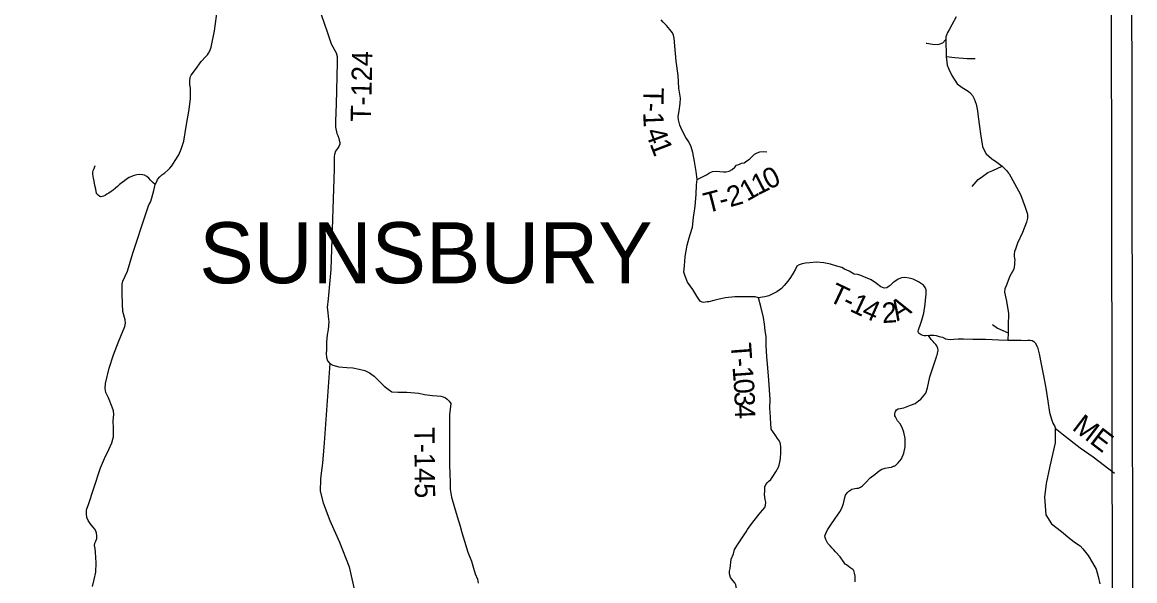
# Model space of a CAD drawing. Extents: x -15 to 405, y -40 to 87.
# Drawn here: x -9.096 to -5.813, y 38.387 to 40.035 of the extents above; entities that cross this region are included whole.
import ezdxf

# ---------------------------------------------------------------- set-up
doc = ezdxf.new("R2010")
doc.units = 0
for name, color, linetype in [('GM_P_State_Location', 7, 'Continuous'), ('GM_X_County_Road_Text', 7, 'Continuous'), ('GM_X_Major_Lake_Text', 7, 'Continuous'), ('GM_X_Minor_Lake', 7, 'Continuous'), ('GM_X_Minor_River', 7, 'Continuous'), ('GM_X_State_Location', 7, 'Continuous'), ('GM_X_Township_Text', 7, 'Continuous')]:
    doc.layers.add(name, color=color, linetype=linetype)

msp = doc.modelspace()

# ---------------------------------------------------------------- linework, layer by layer
at = {"layer": 'GM_P_State_Location'}
for points in [[(-8.2139, 40.0584), (-8.1968, 40.0073), (-8.1843, 39.9714), (-8.1696, 39.9447), (-8.167, 39.9339), (-8.1672, 39.9163), (-8.1697, 39.7939), (-8.1719, 39.7429), (-8.1716, 39.7257), (-8.1682, 39.7073), (-8.1653, 39.7009), (-8.1641, 39.698), (-8.1639, 39.6976)], [(-6.9232, 39.2223), (-6.9337, 39.2246), (-6.9489, 39.2248), (-6.9718, 39.2249), (-6.9934, 39.225), (-7.0214, 39.2215), (-7.0394, 39.2176), (-7.0554, 39.2138), (-7.0698, 39.2104), (-7.0754, 39.21), (-7.0802, 39.2095), (-7.085, 39.2078), (-7.0902, 39.209), (-7.0959, 39.2121), (-7.1053, 39.2264), (-7.1176, 39.2463), (-7.1331, 39.2682), (-7.1405, 39.2862), (-7.1435, 39.2978), (-7.1425, 39.3167), (-7.1396, 39.344), (-7.134, 39.3774), (-7.1283, 39.3987), (-7.1241, 39.4116), (-7.1183, 39.4305), (-7.115, 39.4586), (-7.1102, 39.4924), (-7.1071, 39.5269), (-7.1066, 39.5554), (-7.1044, 39.5715), (-7.1075, 39.5947), (-7.1127, 39.6243), (-7.1174, 39.6511), (-7.1224, 39.6675), (-7.1294, 39.6827), (-7.138, 39.6946), (-7.1499, 39.7177), (-7.1557, 39.7317), (-7.1599, 39.7473), (-7.1604, 39.7573), (-7.1578, 39.7742), (-7.1545, 39.7951), (-7.1539, 39.8111), (-7.1587, 39.8403), (-7.1611, 39.8776), (-7.1665, 39.9208), (-7.1729, 39.9881), (-7.1747, 39.9969), (-7.1775, 40.0037), (-7.1849, 40.014), (-7.1947, 40.0256), (-7.2048, 40.0351), (-7.2109, 40.0422)], [(-6.3711, 39.9846), (-6.3804, 39.9732), (-6.3912, 39.9691), (-6.3968, 39.9682), (-6.41, 39.9692), (-6.4273, 39.9726), (-6.4288, 39.9728)], [(-6.3701, 39.934), (-6.3439, 39.9314), (-6.3077, 39.9279), (-6.2844, 39.9285)], [(-8.1639, 39.6976), (-8.1633, 39.6961), (-8.1611, 39.6873), (-8.1586, 39.6801), (-8.159, 39.6753), (-8.1617, 39.6689), (-8.166, 39.6628), (-8.1688, 39.6588), (-8.1716, 39.6543), (-8.1746, 39.645), (-8.1758, 39.6394), (-8.1761, 39.6025), (-8.1852, 39.3055), (-8.1934, 39.2187), (-8.1963, 39.193), (-8.1945, 39.1782), (-8.1931, 39.1666), (-8.1913, 39.151), (-8.193, 39.1289), (-8.1965, 39.1132), (-8.1982, 39.0915), (-8.1987, 39.0686), (-8.1994, 39.0574), (-8.1984, 39.0461), (-8.1951, 39.0361), (-8.1886, 39.0286), (-8.2049, 38.794), (-8.2105, 38.7342), (-8.2142, 38.7048)], [(-7.1044, 39.5715), (-7.0893, 39.5789), (-7.0773, 39.5851), (-7.0686, 39.5912), (-7.059, 39.5945), (-7.047, 39.5955), (-7.0381, 39.5948), (-7.0273, 39.5933), (-7.0193, 39.5942), (-7.0101, 39.5959), (-7.0017, 39.6005), (-6.9938, 39.6078), (-6.9882, 39.6131), (-6.9819, 39.6155), (-6.9739, 39.6189), (-6.9659, 39.6206), (-6.9619, 39.623), (-6.9579, 39.6259), (-6.95, 39.6308), (-6.9405, 39.6405), (-6.9353, 39.6458), (-6.9274, 39.6499), (-6.9198, 39.6532), (-6.909, 39.6542), (-6.8993, 39.6531)], [(-8.7041, 39.5565), (-8.7109, 39.5618), (-8.7182, 39.5693), (-8.7231, 39.5753), (-8.7288, 39.5804), (-8.7352, 39.584), (-8.7412, 39.5851), (-8.7505, 39.5858), (-8.7581, 39.5845), (-8.7661, 39.5828), (-8.7733, 39.5803), (-8.7809, 39.577), (-8.7884, 39.5721), (-8.7944, 39.5673), (-8.8011, 39.562), (-8.8087, 39.5567), (-8.8155, 39.5506), (-8.8214, 39.5457), (-8.8282, 39.5396), (-8.8337, 39.5356), (-8.841, 39.5308), (-8.8461, 39.5274), (-8.8513, 39.5237), (-8.8563, 39.5217), (-8.8643, 39.5202), (-8.8677, 39.5211), (-8.8725, 39.5247), (-8.8766, 39.5295), (-8.8791, 39.5423), (-8.8824, 39.5531), (-8.8842, 39.5663), (-8.8863, 39.5747), (-8.8868, 39.5811), (-8.8876, 39.5867), (-8.8877, 39.5915), (-8.8865, 39.5976), (-8.8842, 39.6032), (-8.8811, 39.6129)], [(-6.2935, 39.5505), (-6.2752, 39.5714), (-6.2629, 39.5804), (-6.247, 39.5922), (-6.2319, 39.598), (-6.2049, 39.6102)], [(-6.4223, 39.1104), (-6.4294, 39.1097), (-6.4347, 39.11), (-6.4383, 39.1112), (-6.4439, 39.1131), (-6.4467, 39.1143), (-6.4496, 39.1162), (-6.4512, 39.119), (-6.4529, 39.1222), (-6.4517, 39.1275), (-6.4455, 39.144), (-6.4413, 39.1565), (-6.4359, 39.1766), (-6.4322, 39.2035), (-6.4297, 39.2253), (-6.4286, 39.2313), (-6.4291, 39.2389), (-6.4291, 39.2453), (-6.4316, 39.2521), (-6.4369, 39.2593), (-6.4515, 39.2691), (-6.4668, 39.277), (-6.4789, 39.2804), (-6.4917, 39.2819), (-6.5014, 39.2809), (-6.5113, 39.2768), (-6.5217, 39.2703), (-6.5268, 39.2662), (-6.5312, 39.2625), (-6.5352, 39.2584), (-6.5411, 39.2548), (-6.5447, 39.2519), (-6.5531, 39.2506), (-6.5624, 39.2545), (-6.5753, 39.264), (-6.5911, 39.2754), (-6.6084, 39.2824), (-6.6213, 39.2879), (-6.631, 39.2906), (-6.6418, 39.292), (-6.656, 39.3003), (-6.6701, 39.3069), (-6.6782, 39.3116), (-6.6926, 39.3155), (-6.7108, 39.3217), (-6.7312, 39.325), (-6.7537, 39.3267), (-6.7717, 39.3249), (-6.7846, 39.3239), (-6.795, 39.3218), (-6.8034, 39.3197), (-6.8101, 39.3152), (-6.8148, 39.3063), (-6.8211, 39.2946), (-6.8289, 39.2821), (-6.8372, 39.2707), (-6.8479, 39.2582), (-6.8562, 39.2492), (-6.8697, 39.2398), (-6.8813, 39.2333), (-6.8932, 39.2279), (-6.9048, 39.2253), (-6.9116, 39.224), (-6.9232, 39.2223)], [(-6.9561, 38.5378), (-6.9465, 38.552), (-6.9362, 38.565), (-6.922, 38.5837), (-6.9118, 38.5956), (-6.905, 38.6035), (-6.9027, 38.6104), (-6.902, 38.6192), (-6.9037, 38.6273), (-6.9055, 38.6417), (-6.9052, 38.6521), (-6.9054, 38.6642), (-6.9023, 38.6714), (-6.8971, 38.6771), (-6.8928, 38.6812), (-6.8872, 38.6857), (-6.8817, 38.6946), (-6.8723, 38.7083), (-6.8632, 38.7241), (-6.8606, 38.737), (-6.8591, 38.7474), (-6.8573, 38.7659), (-6.8575, 38.7812), (-6.8585, 38.7908), (-6.8614, 38.7988), (-6.8675, 38.8072), (-6.8728, 38.8147), (-6.8797, 38.8243), (-6.8859, 38.8346), (-6.8867, 38.839), (-6.8868, 38.8479), (-6.8887, 38.8699), (-6.8907, 38.8976), (-6.889, 38.9217), (-6.8929, 38.9787), (-6.8962, 39.0151), (-6.8986, 39.0476), (-6.9014, 39.0817), (-6.9013, 39.1066), (-6.904, 39.1254), (-6.9062, 39.1447), (-6.9093, 39.1643), (-6.9169, 39.1963), (-6.9232, 39.2223)], [(-6.233, 39.1436), (-6.2188, 39.1329), (-6.2027, 39.1255), (-6.1869, 39.1185)], [(-6.6382, 38.3842), (-6.6383, 38.393), (-6.6384, 38.4006), (-6.6404, 38.4094), (-6.6425, 38.4171), (-6.6457, 38.4206), (-6.6542, 38.4266), (-6.6643, 38.4345), (-6.6675, 38.4361), (-6.672, 38.4417), (-6.6829, 38.4572), (-6.6963, 38.4728), (-6.7016, 38.4784), (-6.7068, 38.4843), (-6.7121, 38.4903), (-6.7161, 38.4943), (-6.7186, 38.4971), (-6.721, 38.5011), (-6.7251, 38.5083), (-6.7271, 38.5151), (-6.7276, 38.5199), (-6.7252, 38.5267), (-6.7197, 38.5376), (-6.7098, 38.5521), (-6.6972, 38.5711), (-6.6841, 38.5905), (-6.6778, 38.6014), (-6.6727, 38.6147), (-6.6708, 38.6239), (-6.6685, 38.6332), (-6.6673, 38.6392), (-6.6622, 38.6465), (-6.6574, 38.6513), (-6.6479, 38.657), (-6.6391, 38.6591), (-6.6335, 38.6599), (-6.6286, 38.6604), (-6.6223, 38.6633), (-6.6163, 38.6669), (-6.6068, 38.6766), (-6.5941, 38.6904), (-6.5797, 38.7017), (-6.5674, 38.7115), (-6.5598, 38.716), (-6.5502, 38.7197), (-6.539, 38.7214), (-6.531, 38.7226), (-6.5254, 38.7247), (-6.523, 38.7251), (-6.519, 38.7267), (-6.5119, 38.7348), (-6.5016, 38.747), (-6.4945, 38.7639), (-6.4907, 38.7824), (-6.4909, 38.8073), (-6.4947, 38.8253), (-6.4984, 38.8365), (-6.5049, 38.8489), (-6.5134, 38.8592), (-6.5171, 38.8668), (-6.5195, 38.8704), (-6.5212, 38.874), (-6.5212, 38.8792), (-6.5208, 38.8836), (-6.5197, 38.8865), (-6.5165, 38.8917), (-6.5113, 38.8942), (-6.4949, 38.8975), (-6.4749, 38.9053), (-6.4614, 38.9102), (-6.4518, 38.9175), (-6.4447, 38.9232), (-6.4351, 38.9345), (-6.43, 38.9402), (-6.4245, 38.9563), (-6.4184, 38.9889), (-6.3985, 39.048), (-6.3973, 39.052), (-6.3957, 39.0557), (-6.3954, 39.0581), (-6.3942, 39.0633), (-6.3938, 39.0653), (-6.3938, 39.0681), (-6.3947, 39.0725), (-6.3972, 39.0801), (-6.4, 39.0841), (-6.4049, 39.0893), (-6.4085, 39.0929), (-6.4142, 39.0992), (-6.4223, 39.1104)], [(-6.4223, 39.1104), (-6.4179, 39.1116), (-6.4067, 39.1117), (-6.3994, 39.111), (-6.3902, 39.1079), (-6.381, 39.1059), (-6.3721, 39.1012), (-6.3649, 39.0997), (-6.3561, 39.0993), (-6.3476, 39.0998), (-6.334, 39.1007), (-6.3184, 39.1013), (-6.2911, 39.1003), (-6.2543, 39.0998), (-6.2146, 39.0981), (-6.1878, 39.0973)], [(-8.1886, 39.0286), (-8.1801, 39.0235), (-8.1616, 39.0181), (-8.1379, 39.0164), (-8.1211, 39.0154), (-8.1022, 39.0116), (-8.0853, 39.0074), (-8.0716, 39.0004), (-8.0582, 38.9909), (-8.0452, 38.9778), (-8.0286, 38.9616), (-8.0164, 38.9525), (-8.0055, 38.945), (-7.9878, 38.9436), (-7.9614, 38.944), (-7.9261, 38.9404), (-7.9092, 38.9366), (-7.8859, 38.9341), (-7.8718, 38.9331), (-7.861, 38.9316), (-7.8546, 38.9293), (-7.8469, 38.927), (-7.842, 38.923), (-7.8363, 38.9167), (-7.8319, 38.9099), (-7.8354, 38.8769), (-7.8353, 38.836), (-7.8355, 38.7834), (-7.8356, 38.7296), (-7.8337, 38.6767), (-7.8335, 38.6578), (-7.8292, 38.6334), (-7.8204, 38.603), (-7.8124, 38.577), (-7.8037, 38.5486), (-7.799, 38.529), (-7.7915, 38.5038), (-7.781, 38.4714), (-7.7707, 38.4446), (-7.7648, 38.4238), (-7.7594, 38.4075), (-7.7532, 38.3919), (-7.7506, 38.3803)], [(-6.0481, 38.8378), (-6.048, 38.7942), (-6.0644, 38.7247), (-6.0753, 38.6743), (-6.0801, 38.6336), (-6.0761, 38.5812), (-6.0587, 38.5555), (-6.0299, 38.5319), (-6.0052, 38.5119), (-5.9884, 38.4987), (-5.9749, 38.4901), (-5.9663, 38.4815), (-5.9511, 38.462), (-5.9382, 38.4404), (-5.9274, 38.4209), (-5.9209, 38.3993), (-5.9166, 38.3777)]]:
    msp.add_lwpolyline(points, dxfattribs=at)
at = {"layer": 'GM_X_Major_Lake_Text'}
for points in [[(-8.2142, 38.7048), (-8.2164, 38.6871), (-8.2175, 38.651), (-8.2087, 38.6166), (-8.1884, 38.5651), (-8.1603, 38.5012), (-8.1317, 38.4285), (-8.1126, 38.3441), (-8.0996, 38.2684), (-8.0883, 38.1971), (-8.0817, 38.1526), (-8.0819, 38.1029), (-8.09, 38.0442), (-8.103, 37.9922), (-8.1189, 37.9503), (-8.1403, 37.8959)], [(-6.9824, 38.3505), (-6.9882, 38.364), (-6.9908, 38.3753), (-6.9932, 38.3812), (-6.9989, 38.388), (-7.0059, 38.3963), (-7.0096, 38.4079), (-7.0097, 38.4156), (-7.007, 38.4228), (-7.0041, 38.4506), (-6.9979, 38.4667), (-6.9945, 38.4788), (-6.9839, 38.4962), (-6.9716, 38.514), (-6.9602, 38.5318), (-6.9561, 38.5378)]]:
    msp.add_lwpolyline(points, dxfattribs=at)
at = {"layer": 'GM_X_State_Location'}
msp.add_line((-5.8856, 42.1225), (-5.8735, 34.0644), dxfattribs=at)
msp.add_lwpolyline([(-14.9291, 34.0044), (-14.9414, 42.1825), (-5.8257, 42.1825), (-5.8134, 34.0044)], close=True, dxfattribs=at)
at = {"layer": 'GM_X_Township_Text'}
for points in [[(-8.8892, 38.3696), (-8.8839, 38.391), (-8.8789, 38.4119), (-8.8781, 38.4404), (-8.8797, 38.4713), (-8.8811, 38.4825), (-8.8832, 38.4913), (-8.8821, 38.4981), (-8.8793, 38.5042), (-8.8762, 38.5119), (-8.8759, 38.5199), (-8.8769, 38.5283), (-8.881, 38.5379), (-8.8879, 38.5466), (-8.8956, 38.5561), (-8.9014, 38.5653), (-8.9051, 38.5741), (-8.9064, 38.5841), (-8.907, 38.5961), (-8.9, 38.6147), (-8.8858, 38.6578), (-8.865, 38.7202), (-8.8537, 38.7481), (-8.8404, 38.7739), (-8.8319, 38.7945), (-8.8284, 38.805), (-8.8269, 38.8118), (-8.8268, 38.8371), (-8.8283, 38.8592), (-8.8262, 38.8772), (-8.8267, 38.8881), (-8.8305, 38.8997), (-8.8412, 38.9272), (-8.8491, 38.9427), (-8.8516, 38.9543), (-8.8506, 38.9692), (-8.84, 39.0139), (-8.8273, 39.0538), (-8.8126, 39.0921), (-8.7982, 39.1256), (-8.7955, 39.132), (-8.7935, 39.1369), (-8.7916, 39.1469), (-8.7922, 39.1569), (-8.7989, 39.1817), (-8.8004, 39.2042), (-8.8016, 39.2346), (-8.8012, 39.2623), (-8.7993, 39.2716), (-8.7856, 39.3006), (-8.7695, 39.3542), (-8.7314, 39.4694), (-8.7225, 39.4964), (-8.7178, 39.5045), (-8.7136, 39.517), (-8.7074, 39.5384), (-8.7041, 39.5565), (-8.699, 39.5653), (-8.6966, 39.571), (-8.6903, 39.5787), (-8.684, 39.5848), (-8.6757, 39.5913), (-8.6666, 39.5983), (-8.6606, 39.6044), (-8.6551, 39.6117), (-8.6445, 39.627), (-8.6339, 39.644), (-8.6273, 39.661), (-8.6196, 39.6847), (-8.6114, 39.7334), (-8.6032, 39.778), (-8.5992, 39.8105), (-8.6, 39.8402), (-8.6014, 39.8518), (-8.6015, 39.8602), (-8.6004, 39.8731), (-8.5977, 39.8795), (-8.5847, 39.8961), (-8.5678, 39.9196), (-8.5544, 39.9346), (-8.5496, 39.9387), (-8.5465, 39.9444), (-8.543, 39.9508), (-8.5387, 39.9617), (-8.5285, 40.01), (-8.5197, 40.0747)], [(-6.3404, 40.0507), (-6.353, 40.0277), (-6.3612, 40.0128), (-6.3659, 40.0047), (-6.369, 39.997), (-6.3705, 39.9922), (-6.3711, 39.9846), (-6.3701, 39.934), (-6.3684, 39.9176), (-6.3666, 39.9088), (-6.3625, 39.8969), (-6.3534, 39.8781), (-6.3379, 39.8539), (-6.3225, 39.8429), (-6.308, 39.8342), (-6.2999, 39.8275), (-6.2918, 39.8188), (-6.2876, 39.8092), (-6.281, 39.7937), (-6.2775, 39.7737), (-6.2753, 39.7556), (-6.2713, 39.7276), (-6.2682, 39.706), (-6.2652, 39.6872), (-6.2626, 39.6688), (-6.2572, 39.6556), (-6.2523, 39.6473), (-6.236, 39.6334), (-6.2203, 39.622), (-6.2049, 39.6102), (-6.1915, 39.5979), (-6.1859, 39.59)], [(-6.1859, 39.59), (-6.1859, 39.59), (-6.1842, 39.5876), (-6.1678, 39.5593), (-6.1501, 39.5271), (-6.1364, 39.4891), (-6.1314, 39.4752), (-6.1301, 39.4692), (-6.13, 39.4567), (-6.133, 39.4451), (-6.145, 39.4148), (-6.1591, 39.3837), (-6.1656, 39.3652), (-6.1679, 39.3584), (-6.1695, 39.3511), (-6.1694, 39.3439), (-6.1676, 39.3327), (-6.1679, 39.3271), (-6.1682, 39.3202), (-6.1705, 39.3062), (-6.1818, 39.286), (-6.1927, 39.2569), (-6.1966, 39.2488), (-6.1976, 39.2384), (-6.1921, 39.2124), (-6.186, 39.1756), (-6.1867, 39.1406), (-6.1869, 39.1185), (-6.1878, 39.0973), (-6.1721, 39.0975), (-6.1485, 39.0966), (-6.1357, 39.0963), (-6.1289, 39.0968), (-6.1224, 39.0969), (-6.1164, 39.0962), (-6.1116, 39.093), (-6.1071, 39.0895), (-6.1005, 39.0763), (-6.0959, 39.0567), (-6.0899, 39.0263), (-6.0817, 38.9871), (-6.0757, 38.9554), (-6.0696, 38.917), (-6.0648, 38.8837), (-6.0581, 38.8613), (-6.0547, 38.8517), (-6.049, 38.8422), (-6.0481, 38.8378), (-6.024, 38.818), (-5.9749, 38.7796), (-5.9359, 38.7523), (-5.8735, 38.7046)]]:
    msp.add_lwpolyline(points, dxfattribs=at)

# ---------------------------------------------------------------- texts
at = {"layer": 'GM_X_County_Road_Text'}
msp.add_text('SUNSBURY', height=0.18, rotation=0, dxfattribs=at).set_placement((-8.5737, 39.265))
at = {"layer": 'GM_X_Minor_Lake'}
for s, rotation, p in [('M', 322.6014, (-6.001, 38.8347)), ('E', 322.5952, (-5.9493, 38.7951))]:
    msp.add_text(s, height=0.06, rotation=rotation, dxfattribs=at).set_placement(p)
at = {"layer": 'GM_X_Minor_River'}
for s, rotation, p in [('T-124', 88.631, (-8.0675, 39.7402)), ('T', 268.8042, (-7.2628, 39.8427)), ('-', 269.0838, (-7.2638, 39.7975)), ('1', 272.5349, (-7.2641, 39.769)), ('4', 290.0929, (-7.2586, 39.7124)), ('1', 290.924, (-7.2455, 39.6769)), ('0', 26.0368, (-6.8934, 39.54)), ('1', 29.6979, (-6.9575, 39.5053)), ('1', 27.0445, (-6.9261, 39.5233)), ('T', 14.4406, (-7.0765, 39.4713)), ('2', 15.9296, (-7.0075, 39.4891)), ('-', 14.6184, (-7.0328, 39.4825)), ('T', 334.6981, (-6.7202, 39.2139)), ('1', 334.8857, (-6.6572, 39.1841)), ('-', 334.7368, (-6.6796, 39.1947)), ('4', 335.982, (-6.6226, 39.1679)), ('2', 3.5577, (-6.5581, 39.1473)), ('A', 31.0269, (-6.514, 39.1518)), ('T', 274.3455, (-7.0056, 39.0874)), ('-', 274.3364, (-7.0022, 39.0427)), ('1', 274.2606, (-7.0004, 39.0181)), ('0', 273.9789, (-6.9976, 38.9813)), ('3', 271.8634, (-6.9951, 38.9451)), ('4', 271.6864, (-6.9939, 38.9082)), ('T-145', 270.563, (-7.9396, 38.8398))]:
    msp.add_text(s, height=0.06, rotation=rotation, dxfattribs=at).set_placement(p)

doc.saveas('drawing.dxf')
